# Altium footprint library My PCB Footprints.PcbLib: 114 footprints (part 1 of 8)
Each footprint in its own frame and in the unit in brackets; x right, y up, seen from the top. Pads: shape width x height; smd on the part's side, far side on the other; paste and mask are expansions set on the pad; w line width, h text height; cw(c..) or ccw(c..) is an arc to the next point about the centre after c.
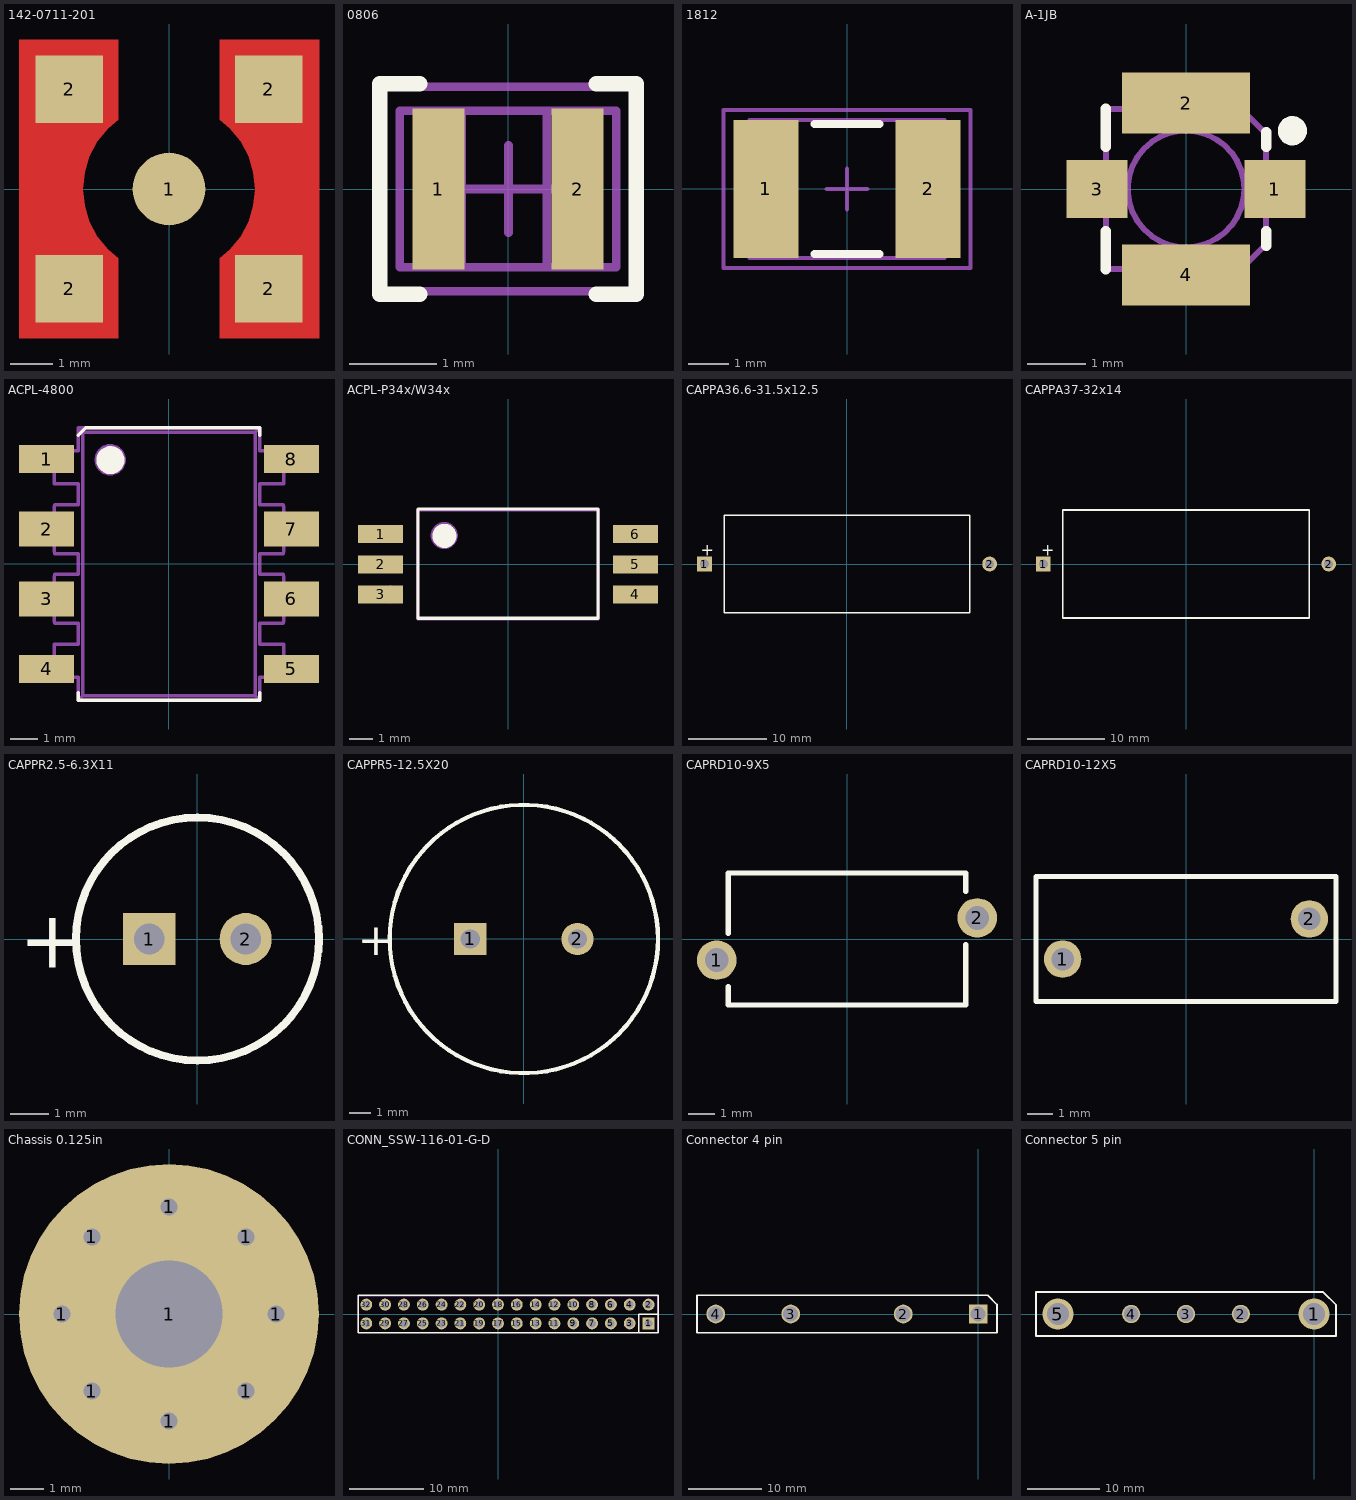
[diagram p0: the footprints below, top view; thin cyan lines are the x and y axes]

## 142-0711-201 [mil] "Emerson Connectivity recommended land pattern"
height 353
pads (5):
  round 68 smd: 1(0,0)
  rect 63x63 smd: 2(-93.5,-93.5) 2(-93.5,93.5) 2(93.5,-93.5) 2(93.5,93.5)
Top Layer:
  region: 140.5,-140 47.5,-140 47.5,-64.83 57.02,-57.02 67.05,-44.8 74.5,-30.86 79.09,-15.73 80.64,0 79.09,15.73 74.5,30.86 67.05,44.8 57.02,57.02 47.5,64.83 47.5,140 140.5,140
  region: -47.5,64.83 -57.02,57.02 -67.05,44.8 -74.5,30.86 -79.09,15.73 -80.64,0 -79.09,-15.73 -74.5,-30.86 -67.05,-44.8 -57.02,-57.02 -47.5,-64.83 -47.5,-140 -140.5,-140 -140.5,140 -47.5,140
Mechanical 5:
  text ".Designator" at -60,-20 h40
3D body: height 288, standoff -50, extent -125,-125 125.09,125.09

## 0806 [mm]
height 1.6
pads (2):
  rect 0.6x1.85 smd: 1(-0.8,0) 2(0.8,0)
Top Overlay:
  lines w0.178: -1.016,-1.21 -1.473,-1.21 -1.473,1.21 -1.016,1.21 ; 1.016,-1.21 1.473,-1.21 1.473,1.21 1.016,1.21
Mechanical 5:
  lines w0.1: -1.245,-0.9 1.245,-0.9 1.245,0.9 -1.245,0.9 -1.245,-0.9
  text ".Designator" at -1.194,-0.432 h1.02
Mechanical 13:
  lines w0.1: -0.533,-0.9 -0.533,0.9 ; 0.445,-0.9 0.445,0.9 ; -1.011,-0.9 0.965,-0.9 0.965,0.9 -1.011,0.9 -1.011,-0.9
Mechanical 15:
  lines w0.1: -0.493,0 0.507,0 ; 0.007,-0.5 0.007,0.5 ; -1.473,-1.175 1.473,-1.175 1.473,1.175 -1.473,1.175 -1.473,-1.175
3D body: height 1.6, standoff 0, extent -1.011,-0.91 -0.513,0.889
3D body: height 1.6, standoff 0, extent -0.508,-0.91 0.457,0.889
3D body: height 1.6, standoff 0, extent 0.462,-0.91 0.961,0.889

## 1812 [mm]
height 1.35
pads (2):
  rect 1.6x3.4 smd: 1(-2,0) 2(2,0)
Top Overlay:
  lines w0.2: -0.8,-1.6 0.8,-1.6 ; -0.8,1.6 0.8,1.6
Mechanical 5:
  lines w0.1: -2.4,-1.7 2.4,-1.7 2.4,1.7 -2.4,1.7 -2.4,-1.7
  text ".Designator" at -1.875,-0.5 h1.02
Mechanical 13:
  lines w0.1: -1.9,-1.7 -1.9,1.7 ; 1.9,-1.7 1.9,1.7 ; -2.4,-1.7 -2.4,1.7 2.4,1.7 2.4,-1.7 -2.4,-1.7
Mechanical 15:
  lines w0.1: -0.5,0 0.5,0 ; 0,-0.5 0,0.5 ; -3.05,-1.95 -3.05,1.95 3.05,1.95 3.05,-1.95 -3.05,-1.95
3D body: height 1.35, standoff 0, extent -2.399,-1.699 -1.901,1.699
3D body: height 1.35, standoff 0, extent -1.899,-1.699 1.899,1.699
3D body: height 1.35, standoff 0, extent 1.901,-1.699 2.399,1.699

## A-1JB [mm] "Amphenol recommended land pattern"
height 1.25
pads (4):
  rect 1.05x1 smd: 1(1.525,0) 3(-1.525,0)
  rect 2.2x1.05 smd: 2(0,1.475) 4(0,-1.475)
Top Overlay:
  circle w0.25: c1.825,1 r0.125
  lines w0.178: -1.375,-1.375 -1.375,-0.725 ; -1.375,0.725 -1.375,1.375 ; 1.375,-0.975 1.375,-0.725 ; 1.375,0.725 1.375,0.975
Mechanical 5:
  text ".Designator" at -1.524,-0.508 h1.02
Mechanical 13:
  circle w0.1: c0,0 r1
  lines w0.025: 0.95,1.35 0.95,1.375
  lines w0.1: -1.375,-1.375 0.95,-1.375 1.375,-0.95 1.375,0.95 0.95,1.375 -1.375,1.375 -1.375,-1.375
3D body: height 0.35, standoff 0, extent -1.375,-1.375 1.375,1.375
3D body: height 1.25, standoff 0.35, extent -1.008,-1.008 1.008,1.008

## ACPL-4800 [mm] "AVAGO"
height 4.35
pads (8):
  rect 2x1.016 smd: 1(-4.45,3.81) 4(-4.45,-3.81) 5(4.45,-3.81) 8(4.45,3.81)
  rect 2x1.27 smd: 2(-4.45,1.27) 3(-4.45,-1.27) 6(4.45,-1.27) 7(4.45,1.27)
Top Overlay:
  circle w0.508: c-2.129,3.775 r0.254
  lines w0.127: -3.3,-4.675 -3.3,-4.95 3.3,-4.95 3.3,-4.675 ; -3.3,4.675 -3.025,4.95 3.3,4.95 3.3,4.675
Mechanical 5:
  lines w0.127: -3.3,-4.107 -3.3,-4.95 ; -3.3,-2.917 -3.3,-2.16 ; -3.3,-0.38 -3.3,0.38 ; -3.3,2.16 -3.3,2.917 ; -3.3,4.107 -3.3,4.95 ; -3.296,-4.107 -3.9,-4.107 -4.171,-4.107 -4.668,-4.107 -4.95,-4.107 -4.95,-3.482 -4.668,-3.482 -4.171,-3.482 -4.171,-2.917 -3.9,-2.917 -3.296,-2.917 ; -3.296,-2.16 -3.9,-2.16 -4.159,-2.16 -4.171,-2.091 -4.171,-1.595 -4.668,-1.595 -4.95,-1.595 -4.95,-0.945 -4.668,-0.945 -4.171,-0.945 -4.171,-0.449 -4.159,-0.38 -3.9,-0.38 -3.296,-0.38 ; -3.296,0.38 -3.9,0.38 -4.159,0.38 -4.171,0.449 -4.171,0.945 -4.668,0.945 -4.95,0.945 -4.95,1.595 -4.668,1.595 -4.171,1.595 -4.171,2.091 -4.159,2.16 -3.9,2.16 -3.296,2.16 ; -3.296,2.917 -3.9,2.917 -4.171,2.917 -4.171,3.482 -4.668,3.482 -4.95,3.482 -4.95,4.107 -4.668,4.107 -4.171,4.107 -3.9,4.107 -3.296,4.107 ; 3.296,-4.107 3.9,-4.107 4.171,-4.107 4.668,-4.107 4.95,-4.107 4.95,-3.482 4.668,-3.482 4.171,-3.482 4.171,-2.917 3.9,-2.917 3.296,-2.917 ; 3.296,-2.16 3.9,-2.16 4.159,-2.16 4.171,-2.091 4.171,-1.595 4.668,-1.595 4.95,-1.595 4.95,-0.945 4.668,-0.945 4.171,-0.945 4.171,-0.449 4.159,-0.38 3.9,-0.38 3.296,-0.38 ; 3.296,0.38 3.9,0.38 4.159,0.38 4.171,0.449 4.171,0.945 4.668,0.945 4.95,0.945 4.95,1.595 4.668,1.595 4.171,1.595 4.171,2.091 4.159,2.16 3.9,2.16 3.296,2.16 ; 3.296,2.917 3.9,2.917 4.171,2.917 4.171,3.482 4.668,3.482 4.95,3.482 4.95,4.107 4.668,4.107 4.171,4.107 3.9,4.107 3.296,4.107 ; 3.3,-4.107 3.3,-4.95 ; 3.3,-2.917 3.3,-2.16 ; 3.3,-0.38 3.3,0.38 ; 3.3,2.16 3.3,2.917 ; 3.3,4.107 3.3,4.95 ; -3.3,-4.95 -3.139,-4.789 ; -3.3,-4.95 3.3,-4.95 ; -3.3,4.95 3.3,4.95 ; -3.3,4.95 -3.139,4.789 ; -3.139,-4.789 -3.139,4.789 ; -3.139,-4.789 3.139,-4.789 ; -3.139,4.789 3.139,4.789 ; 3.139,-4.789 3.3,-4.95 ; 3.139,-4.789 3.139,4.789 ; 3.139,4.789 3.3,4.95 ; -2.139,3.281 cw(c-2.139,3.789) -2.139,4.297 cw(c-2.139,3.789) -2.139,3.281
  text ".Designator" at -1.925,-0.525 h1.02
3D body: height 4.34, standoff 0.02, extent -4.95,-4.95 4.95,4.95

## ACPL-P34x/W34x [mm] "Avago Stretched SO-6 Package"
height 3.18
pads (6):
  rect 1.905x0.76 smd: 1(-5.372,1.27) 2(-5.372,0) 3(-5.372,-1.27) 4(5.372,-1.27) 5(5.372,0) 6(5.372,1.27)
Top Overlay:
  circle w0.508: c-2.679,1.2 r0.254
  lines w0.127: -3.8,2.3 -3.8,-2.275 3.8,-2.275 ; -3.8,2.325 3.8,2.325 3.8,-2.25
Mechanical 5:
  lines w0.127: -4.95,-1.595 -4.95,-0.945 ; 3.81,2.3 -3.81,2.3 -3.81,-2.3 3.81,-2.3 3.81,2.325 ; -2.689,0.706 cw(c-2.689,1.214) -2.689,1.722 cw(c-2.689,1.214) -2.689,0.706
  text ".Designator" at -1.925,-0.525 h1.02

## CAPPA36.6-31.5x12.5 [mm] "Capacitor, Electrolytic, Axial; Body 31.5 x 12.5 mm (LxDia. max), Lead Dia. 0.8 mm (typ)"
height 12.5
pads (2):
  rect 1.9x1.9 hole 1.15: 1(-18.3,0)
  round 1.9 hole 1.15: 2(18.3,0)
Top Overlay:
  lines w0.2: -15.75,-6.25 -15.75,6.25 15.75,6.25 15.75,-6.25 -15.75,-6.25
  text "+" at -18.8,1.075 h1.5

## CAPPA37-32x14 [mm] "Capacitor, Axial; Body 32 x 14 mm (LxDia. max), Lead Dia. 0.8 mm (typ)"
height 14
pads (2):
  rect 1.9x1.9 hole 1.15: 1(-18.5,0)
  round 1.9 hole 1.15: 2(18.5,0)
Top Overlay:
  lines w0.2: -16,-7 -16,7 16,7 16,-7 -16,-7
  text "+" at -18.8,1.075 h1.5

## CAPPR2.5-6.3X11 [mm] "Capacitor, Electrolytic, Radial; Body 6.3 x 11 mm (Dia.xH typ); Pin Spacing 2.5 mm (typ)"
height 12
pads (2):
  rect 1.35x1.35 hole 0.8: 1(-1.25,0)
  round 1.35 hole 0.8: 2(1.25,0)
Top Overlay:
  circle w0.2: c0,0 r3.15
  text "+" at -4.625,-0.75 h1.5

## CAPPR5-12.5X20 [mm] "Capacitor, Electrolytic, Radial; Body 12.5 x 20 mm (Dia.xH typ); Pin Spacing 5 mm (typ)"
height 21.5
pads (2):
  rect 1.5x1.5 hole 0.9: 1(-2.5,0)
  round 1.5 hole 0.9: 2(2.5,0)
Top Overlay:
  circle w0.2: c0,0 r6.25
  text "+" at -7.725,-0.75 h1.5

## CAPRD10-9X5 [mm] "Capacitor, Ceramic, Thru-Hole, Disc; Body 9 x 5 mm (LxW max) Pin Spacing 10 mm (typ)"
height 12
pads (2):
  round 1.5 hole 0.9: 1(-4.936,-0.8) 2(4.936,0.8)
Top Overlay:
  lines w0.2: -4.5,-1.81 -4.5,-2.5 4.5,-2.5 4.5,-0.21 ; -4.5,0.21 -4.5,2.5 4.5,2.5 4.5,1.81

## CAPRD10-12X5 [mm] "Capacitor, Ceramic, Thru-Hole, Disc; Body 12 x 5 mm (LxW max) Pin Spacing 10 mm (typ)"
height 15
pads (2):
  round 1.5 hole 0.9: 1(-4.936,-0.8) 2(4.936,0.8)
Top Overlay:
  lines w0.2: -6,-2.5 6,-2.5 6,2.5 -6,2.5 -6,-2.5

## Chassis 0.125in [mil] "Chassis 0.125in"
height 200
pads (9):
  round 40 hole 20: 1(-125,0) 1(-90,-90) 1(-90,90) 1(0,-125) 1(0,125) 1(90,-90) 1(90,90) 1(125,0)
  round 350 hole 125: 1(0,0)
Mechanical 5:
  text ".Designator" at -60,-20 h40

## CONN_SSW-116-01-G-D [mm] "SAMTEC 16x2, 100mil, female, TH"
height 8.51
pads (32):
  rect 1.6x1.6 hole 1.04: 1(20.32,-1.27)
  round 1.6 hole 1.04: 2(20.32,1.27) 3(17.78,-1.27) 4(17.78,1.27) 5(15.24,-1.27) 6(15.24,1.27) 7(12.7,-1.27) 8(12.7,1.27) 9(10.16,-1.27) 10(10.16,1.27) 11(7.62,-1.27) 12(7.62,1.27) 13(5.08,-1.27) 14(5.08,1.27) 15(2.54,-1.27) 16(2.54,1.27) 17(0,-1.27) 18(0,1.27) 19(-2.54,-1.27) 20(-2.54,1.27) 21(-5.08,-1.27) 22(-5.08,1.27) 23(-7.62,-1.27) 24(-7.62,1.27) 25(-10.16,-1.27) 26(-10.16,1.27) 27(-12.7,-1.27) 28(-12.7,1.27) 29(-15.24,-1.27) 30(-15.24,1.27) 31(-17.78,-1.27) 32(-17.78,1.27)
Top Overlay:
  lines w0.17: 19,-2.5 19,0 21.5,0 ; -18.9,-2.5 21.6,-2.5 21.6,2.5 -18.9,2.5 -18.9,0 -18.9,-2.5
Mechanical 5:
  rectangle: 19.8,-1.8 20.9,-0.7
  lines w0.1: -18.9,-2.475 21.56,-2.475 21.56,2.475 -18.9,2.475 -18.9,-2.475
  text ".Designator" at -2.1,-0.5 h1.02
3D body: height 8.55, standoff 8, extent -18.077,0.971 -17.48,1.57
3D body: height 8.55, standoff 8, extent -15.537,-1.569 -14.94,-0.97
3D body: height 8.55, standoff 8, extent -15.537,0.971 -14.94,1.57
3D body: height 8.55, standoff 8, extent -18.077,-1.569 -17.48,-0.97
3D body: height 8.55, standoff 8, extent 12.403,-1.569 13,-0.97
3D body: height 8.55, standoff 8, extent 14.943,0.971 15.54,1.57
3D body: height 8.55, standoff 8, extent 20.023,0.971 20.62,1.57
3D body: height 8.55, standoff 8, extent 20.023,-1.569 20.62,-0.97
3D body: height 8.55, standoff 8, extent 14.943,-1.569 15.54,-0.97
3D body: height 8.55, standoff 8, extent 17.483,0.971 18.08,1.57
3D body: height 8.55, standoff 8, extent 17.483,-1.569 18.08,-0.97
3D body: height 8.55, standoff 8, extent 9.863,0.971 10.46,1.57
3D body: height 8.55, standoff 8, extent 9.863,-1.569 10.46,-0.97
3D body: height 8.55, standoff 8, extent 12.403,0.971 13,1.57
3D body: height 8.55, standoff 8, extent 4.783,-1.569 5.38,-0.97
3D body: height 8.55, standoff 8, extent 7.323,0.971 7.92,1.57
3D body: height 8.55, standoff 8, extent 7.323,-1.569 7.92,-0.97
3D body: height 8.55, standoff 8, extent 2.243,0.971 2.84,1.57
3D body: height 8.55, standoff 8, extent 2.243,-1.569 2.84,-0.97
3D body: height 8.55, standoff 8, extent 4.783,0.971 5.38,1.57
3D body: height 8.55, standoff 8, extent -2.837,-1.569 -2.24,-0.97
3D body: height 8.55, standoff 8, extent -0.297,0.971 0.3,1.57
3D body: height 8.55, standoff 8, extent -0.297,-1.569 0.3,-0.97
3D body: height 8.55, standoff 8, extent -5.377,0.971 -4.78,1.57
3D body: height 8.55, standoff 8, extent -5.377,-1.569 -4.78,-0.97
3D body: height 8.55, standoff 8, extent -2.837,0.971 -2.24,1.57
3D body: height 8.55, standoff 8, extent -10.457,-1.569 -9.86,-0.97
3D body: height 8.55, standoff 8, extent -7.917,0.971 -7.32,1.57
3D body: height 8.55, standoff 8, extent -7.917,-1.569 -7.32,-0.97
3D body: height 8.55, standoff 8, extent -12.997,-1.569 -12.4,-0.97
3D body: height 8.55, standoff 8, extent -10.457,0.971 -9.86,1.57
3D body: height 8.55, standoff 8, extent -12.997,0.971 -12.4,1.57
3D body: height 8.51, standoff 0, extent -18.9,-2.474 21.559,2.474
3D body: height 3, standoff -2, extent -18.18,1.07 -17.38,1.47
3D body: height 3, standoff -2, extent -18.18,-1.47 -17.38,-1.07
3D body: height 3, standoff -2, extent -15.64,1.07 -14.84,1.47
3D body: height 3, standoff -2, extent -15.64,-1.47 -14.84,-1.07
3D body: height 3, standoff -2, extent 19.92,-1.47 20.72,-1.07
3D body: height 3, standoff -2, extent 17.38,-1.47 18.18,-1.07
3D body: height 3, standoff -2, extent 14.84,-1.47 15.64,-1.07
3D body: height 3, standoff -2, extent 9.76,-1.47 10.56,-1.07
3D body: height 3, standoff -2, extent 12.3,-1.47 13.1,-1.07
3D body: height 3, standoff -2, extent 19.92,1.07 20.72,1.47
3D body: height 3, standoff -2, extent 14.84,1.07 15.64,1.47
3D body: height 3, standoff -2, extent 17.38,1.07 18.18,1.47
3D body: height 3, standoff -2, extent 7.22,-1.47 8.02,-1.07
3D body: height 3, standoff -2, extent 14.84,1.07 15.64,1.47
3D body: height 3, standoff -2, extent 12.3,1.07 13.1,1.47
3D body: height 3, standoff -2, extent 9.76,1.07 10.56,1.47
3D body: height 3, standoff -2, extent 7.22,1.07 8.02,1.47
3D body: height 3, standoff -2, extent 2.14,-1.47 2.94,-1.07
3D body: height 3, standoff -2, extent 4.68,1.07 5.48,1.47
3D body: height 3, standoff -2, extent 2.14,1.07 2.94,1.47
3D body: height 3, standoff -2, extent 4.68,-1.47 5.48,-1.07
3D body: height 3, standoff -2, extent -0.4,1.07 0.4,1.47
3D body: height 3, standoff -2, extent -0.4,-1.47 0.4,-1.07
3D body: height 3, standoff -2, extent -2.94,1.07 -2.14,1.47
3D body: height 3, standoff -2, extent -2.94,-1.47 -2.14,-1.07
3D body: height 3, standoff -2, extent -5.48,-1.47 -4.68,-1.07
3D body: height 3, standoff -2, extent -5.48,1.07 -4.68,1.47
3D body: height 3, standoff -2, extent -8.02,-1.47 -7.22,-1.07
3D body: height 3, standoff -2, extent -8.02,1.07 -7.22,1.47
3D body: height 3, standoff -2, extent -10.56,-1.47 -9.76,-1.07
3D body: height 3, standoff -2, extent -10.56,1.07 -9.76,1.47
3D body: height 3, standoff -2, extent -13.1,1.07 -12.3,1.47
3D body: height 3, standoff -2, extent -13.1,-1.47 -12.3,-1.07

## Connector 4 pin [mil] "Connector 4 pin"
height 200
pads (4):
  rect 100x100 hole 80: 1(0,0)
  round 100 hole 80: 2(-400,0) 3(-1000,0) 4(-1400,0)
Top Overlay:
  lines w10: -1500,-100 100,-100 100,50 50,100 -1500,100 -1500,-100
Mechanical 5:
  text ".Designator" at -900,-10 h40

## Connector 5 pin [mil] "Connector 5 pin"
height 200
pads (5):
  round 170 hole 120: 1(0,0) 5(-1400,0)
  round 100 hole 80: 2(-400,0) 3(-700,0) 4(-1000,0)
Top Overlay:
  lines w10: -1520,-120 120,-120 120,50 50,120 -1520,120 -1520,-120
Mechanical 5:
  text ".Designator" at -930,-20 h40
